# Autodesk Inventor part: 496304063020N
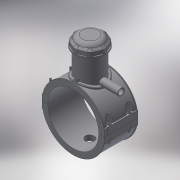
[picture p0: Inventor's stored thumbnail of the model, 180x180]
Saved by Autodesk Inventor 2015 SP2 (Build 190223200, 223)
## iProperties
Created: 2017-07
Part Number: 496304063020N
Material: Generic
Description: PLASSON TAPPING SADDLE 63x20
Document SubType Name: Modeling
Designer: KIM
Mass: 267.781 g
Surface Area: 914.907 cm^2
Volume: 267.781 cm^3
Density: 1 g/cm^3
Appearance: Default
Author: KIM
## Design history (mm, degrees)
derived "496304.ipt"
feature "Solid1::496304.ipt"
feature "Solid2::496304.ipt"
feature "Solid4::496304.ipt"
feature "Solid5::496304.ipt"
tag "TaggingFeature1"
body "Solid1"
body "Solid2"
other parameters: "d0" = 63, "d3" = 15.75, "d4" = 118, "d5" = 0, "d6" = 0.1, "d8" = 0, "d19" = 6, "d20" = 6, "d21" = 70.8, "d23" = 0, "d24" = 35.4, "d26" = 0, "d29" = 3, "d30" = 21, "d31" = 6, "d32" = 0, "d33" = 0, "d34" = 0.6, "d40" = 42.588, "d41" = 56.7, "d43" = 0, "d45" = 0, "d47" = 111.75, "d70" = 15, "d72" = 0, "d73" = 6, "d75" = 5, "d76" = 0, "d77" = 3.15, "d78" = 61.5, "d79" = 15, "d80" = 47.2, "d82" = 5 deg, "d84" = 4, "d85" = 14, "d86" = 0, "d87" = 3, "d88" = 0, "d89" = 1, "d90" = 1, "d91" = 94.4, "d92" = 0, "d93" = 0.5, "d94" = 33.15789, "d96" = 83.538, "d97" = 2.36, "d98" = 0, "d102" = 0.63, "d120" = 140 deg, "d121" = 24.228, "d122" = 20 deg, "d123" = 163.8, "d124" = 49.14, "d126" = 0, "d143" = 64.89, "d145" = 14.53846, "d149" = 0.945, "d150" = 15.99231, "d153" = 118, "d154" = 0, "d156" = 40.95, "d157" = 160 deg, "d159" = 3.78, "d161" = 0.945, "d162" = 70.8, "d163" = 0, "d164" = 31.5, "d167" = 6.3, "d168" = 39.95122, "d170" = 3.375, "d172" = 0, "d173" = 1, "d175" = 31.5, "d176" = 20 deg, "d177" = 4.41, "d178" = 18.9, "d180" = 0, "d183" = 7.56, "d184" = 3.528, "d185" = 38.35, "d186" = 38.35, "d187" = 40.95, "d188" = 5.67, "d189" = 4.41, "d190" = 0, "d191" = 61.425, "d193" = 6.3, "d194" = 4.13, "d195" = 90 deg, "d197" = 0, "d199" = 0, "d200" = 9.45, "d202" = 0, "d204" = 53.865, "d205" = 39.69, "d206" = 48.195, "d207" = 67.5, "d208" = 70.2, "d209" = 83.7, "d210" = 48.762, "d211" = 56.7, "d212" = 45.36, "d213" = 0, "d216" = 0, "d217" = 6.3, "d218" = 6.3, "d219" = 1.26, "d222" = 63, "d224" = 0, "d230" = 3.78, "d233" = 6, "d237" = 35.4, "d238" = 6.02433, "d240" = 35.4, "d241" = 35.4, "d242" = 35.4, "d243" = 6, "d244" = 35.4, "d245" = 35.4, "d246" = 35.4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
